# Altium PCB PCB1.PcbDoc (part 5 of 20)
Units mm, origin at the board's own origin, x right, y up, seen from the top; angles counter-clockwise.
Board outline 294.51 x 138.18 mm, 12 copper layers (Top Layer 1 _Signal, L2_GND, L3_Signals, L4_GND, L5_POWER, L6_Signals, L7_GND, L8_Signals, L9_GND, L10_POWER, L11_GND, Bottom Layer_Signals), stack 1.788 mm thick; 1254 components, 836 nets, 5699 pads, 2073 vias.
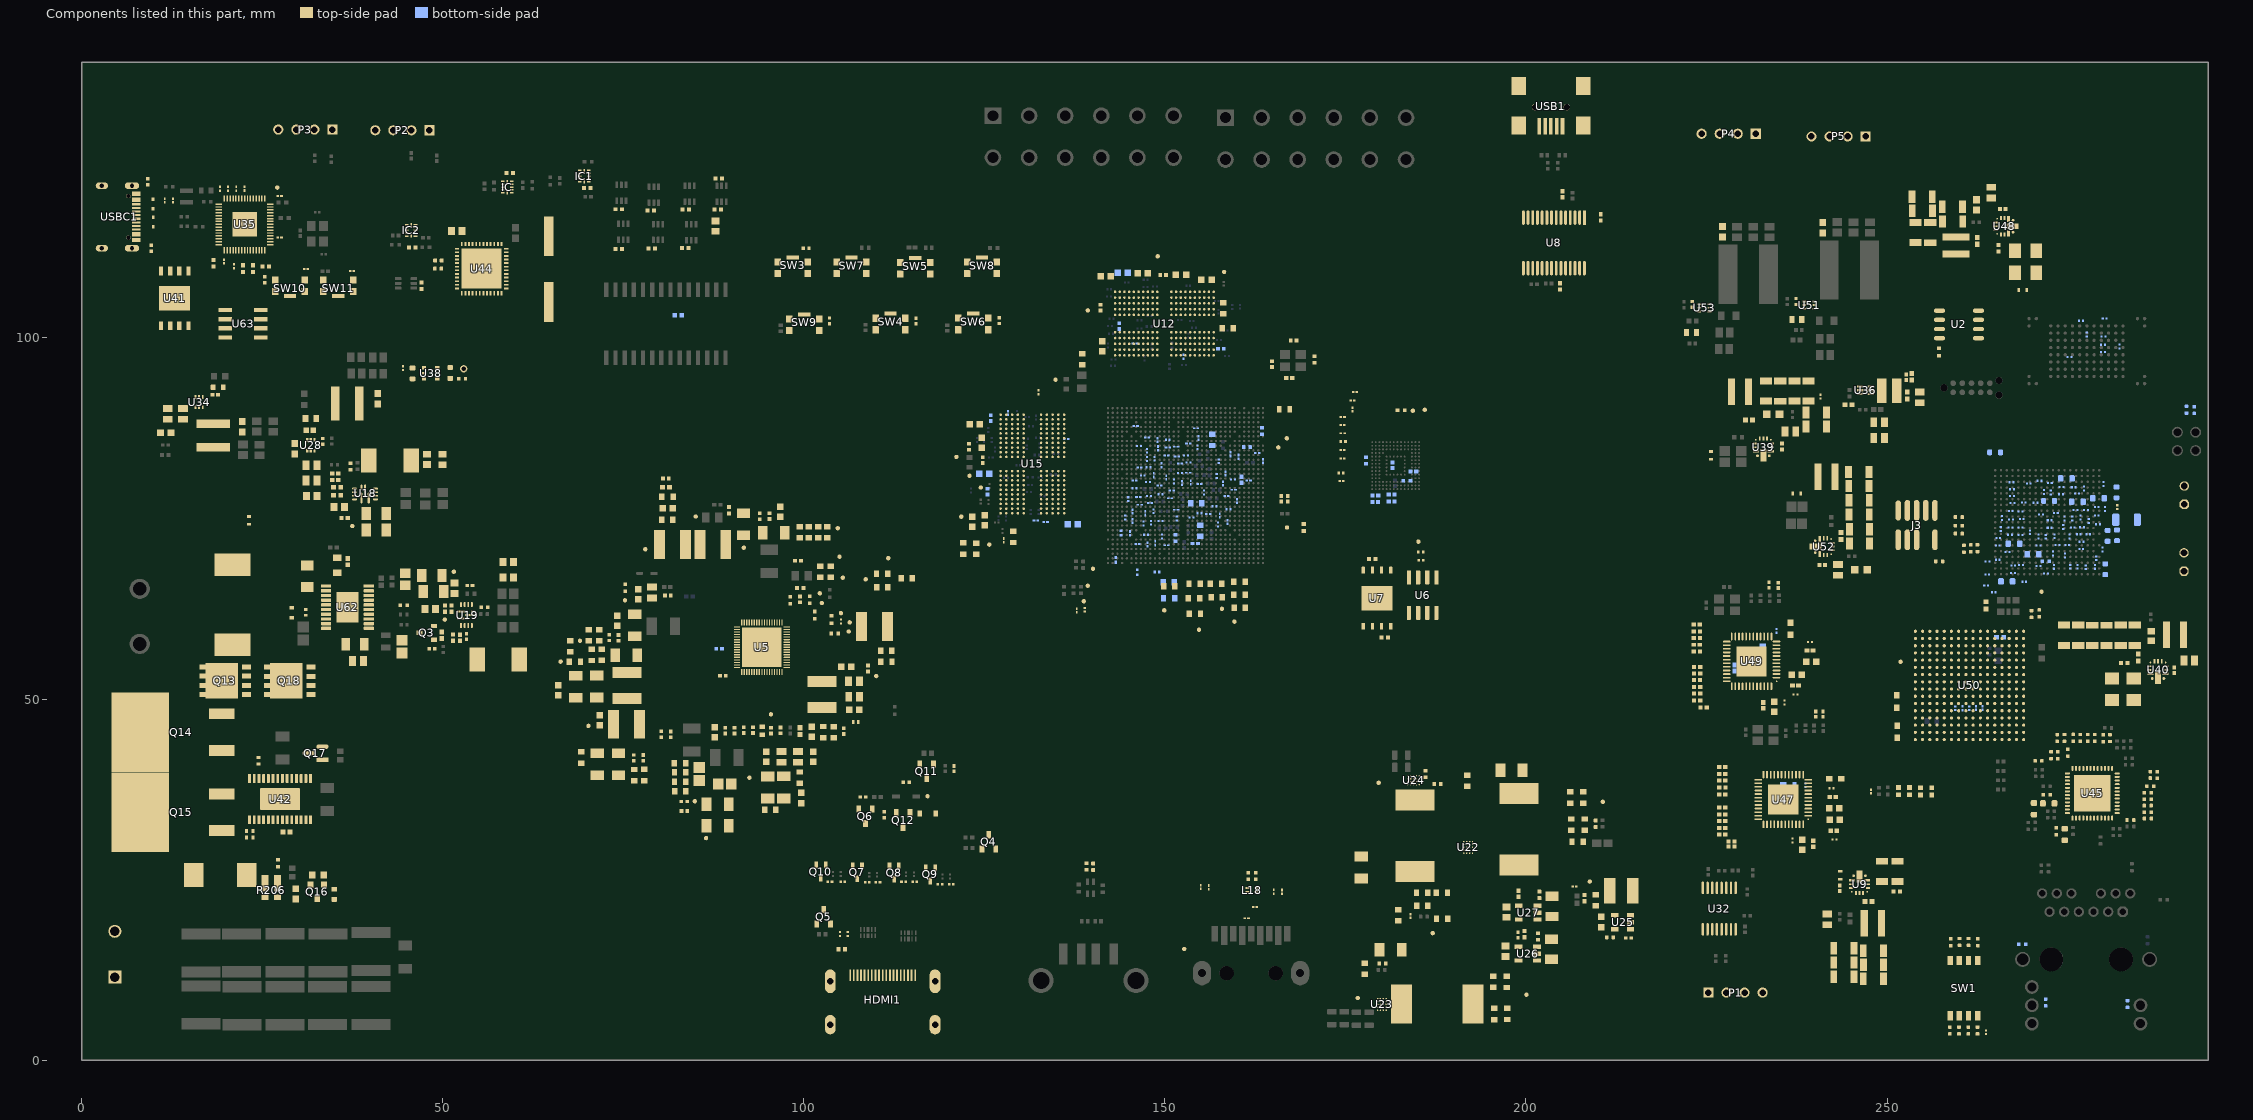
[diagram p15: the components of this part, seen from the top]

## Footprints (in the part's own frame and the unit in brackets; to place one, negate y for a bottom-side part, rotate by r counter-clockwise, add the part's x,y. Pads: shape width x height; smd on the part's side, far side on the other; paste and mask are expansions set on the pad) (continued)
FP-GRM155-0_1-MFG [mm]
  rect 0.4x0.5 smd paste+0 mask+0: 1(-0.4,0) 2(0.4,0)
  silkscreen extent -0.52,-0.62 0.52,0.63, body extent -0.7,-0.4 0.7,0.4, height 0.25
FP-GRM186-0_2-MFG [mm]
  rect 0.75x0.9 smd paste+0 mask+0: 1(-0.775,0) 2(0.775,0)
  silkscreen extent -0.02,-0.5 0.03,0.5, body extent -1.25,-0.6 1.25,0.6, height 0.25
FP-GRM188-0_1-e0_2_0_5-IPC_B [mm]
  rect 0.959x0.912 smd paste+0 mask+0: 1(-0.727,0) 2(0.727,0)
  silkscreen extent -1.21,-0.86 1.21,0.86, body extent -1.46,-0.71 1.46,0.71, height 0.25
FP-GRM188-0_2-MFG [mm]
  rect 0.75x0.9 smd paste+0 mask+0: 1(-0.775,0) 2(0.775,0)
  silkscreen extent -0.9,-0.9 0.9,0.9, body extent -0.8,-0.4 0.8,0.4, height 1
FP-KMR442G_ULC_LFS-MFG [mm]
  rect 0.9x1 smd paste+0 mask+0: 1(-2.05,0.8) 2(2.05,0.8) 3(-2.05,-0.8) 4(2.05,-0.8)
  rect 1.7x0.55 smd paste+0 mask+0: 5(0,1.425)
  silkscreen extent -3.22,-1.4 1.22,0.95, body extent -2.6,-1.5 2.6,1.8, height 0.25
FP-MCS0402-IPC_A [mm]
  rect 0.665x0.672 smd paste+0 mask+0: 1(-0.504,0) 2(0.504,0)
  silkscreen extent -0.84,-0.74 0.84,0.74, body extent -1.04,-0.54 1.04,0.54, height 0.25
FP-MCS0402-IPC_C [mm]
  rect 0.465x0.472 smd paste+0 mask+0: 1(-0.404,0) 2(0.404,0)
  silkscreen extent -0.64,-0.67 0.64,0.67, body extent -0.74,-0.38 0.74,0.38, height 0.25
FP-MCT0603-MFG [mm]
  rect 0.7x0.95 smd paste+0 mask+0: 1(-0.675,0) 2(0.675,0)
  silkscreen extent -0.8,-0.85 0.8,0.85, body extent -1.12,-0.58 1.12,0.58, height 0.25
FP-MCZ1210AH-MFG [mm]
  rect 0.3x0.5 smd paste+0 mask+0: 1(-0.275,-0.613) 2(0.275,-0.613) 3(0.275,0.612) 4(-0.275,0.612)
  silkscreen extent -0.83,-1.56 0.82,0.7, body extent -0.67,-0.96 0.67,0.96, height 0.25
FP-NRS5030-H_3_1-MFG [mm]
  rect 1.5x4 smd paste+0 mask+0: 1(-1.8,0) 2(1.8,0)
  silkscreen extent -2.55,-2.55 2.55,2.55, body extent -2.65,-2.65 2.65,2.65, height 0.25
FP-PS0612-MFG [mm]
  rect 1x0.8 smd paste+0 mask+0: 1(-0.875,1.35) 2(0.875,1.35)
  rect 1x2.32 smd paste+0 mask+0: 3(-0.875,-0.59) 4(0.875,-0.59)
  silkscreen extent -2.23,-2.25 0.88,2.22, body extent -1.48,-1.85 1.48,1.85, height 0.25
FP-RC0603-0_55-IPC_A [mm]
  rect 1.059x1.012 smd paste+0 mask+0: 1(-0.877,0) 2(0.877,0)
  silkscreen extent -1.41,-0.91 1.41,0.91, body extent -1.91,-1.01 1.91,1.01, height 0.25
FP-RC1005-IPC_A [mm]
  rect 0.715x0.672 smd paste+0 mask+0: 1(-0.479,0) 2(0.479,0)
  silkscreen extent -0.84,-0.74 0.84,0.74, body extent -1.04,-0.54 1.04,0.54, height 0.25
FP-RGZ0048B-IPC_A [mm]
  round 0.215 smd paste+0 mask+0: 1(-3.463,2.75)
  rrect100% 1.057x0.239 smd paste+0 mask+0: 2(-3.451,2.25) 3(-3.451,1.75) 4(-3.451,1.25) 5(-3.451,0.75) 6(-3.451,0.25) 7(-3.451,-0.25) 8(-3.451,-0.75) 9(-3.451,-1.25) 10(-3.451,-1.75) 11(-3.451,-2.25) 12(-3.451,-2.75) 25(3.451,-2.75) 26(3.451,-2.25) 27(3.451,-1.75) 28(3.451,-1.25) 29(3.451,-0.75) 30(3.451,-0.25) 31(3.451,0.25) 32(3.451,0.75) 33(3.451,1.25) 34(3.451,1.75) 35(3.451,2.25) 36(3.451,2.75)
  rrect100% 0.239x1.057 smd paste+0 mask+0: 13(-2.75,-3.451) 14(-2.25,-3.451) 15(-1.75,-3.451) 16(-1.25,-3.451) 17(-0.75,-3.451) 18(-0.25,-3.451) 19(0.25,-3.451) 20(0.75,-3.451) 21(1.25,-3.451) 22(1.75,-3.451) 23(2.25,-3.451) 24(2.75,-3.451) 37(2.75,3.451) 38(2.25,3.451) 39(1.75,3.451) 40(1.25,3.451) 41(0.75,3.451) 42(0.25,3.451) 43(-0.25,3.451) 44(-0.75,3.451) 45(-1.25,3.451) 46(-1.75,3.451) 47(-2.25,3.451) 48(-2.75,3.451)
  rect 4.2x4.2 smd paste-1000 mask+0: 49(0,0)
  Top Layer 1 _Signal region: -3.979,2.87 -3.042,2.87 -2.996,2.861 -2.957,2.835 -2.931,2.796 -2.922,2.75 -2.922,2.75 -2.938,2.69 -2.982,2.646 -3.042,2.63 -3.042,2.63 -3.979,2.63
  silkscreen extent -4.68,-3.5 3.5,3.5, body extent -4.48,-4.48 4.48,4.48, height 0.25
FP-RMCF0201-IPC_C [mm]
  rect 0.354x0.263 smd paste+0 mask+0: 1(-0.254,0) 2(0.254,0)
  silkscreen extent -0.43,-0.56 0.43,0.57, body extent -0.3,-0.15 0.3,0.15, height 0.26
FP-RMCF0603-IPC_B [mm]
  rect 1.006x0.958 smd paste+0 mask+0: 1(-0.701,0) 2(0.701,0)
  silkscreen extent -1.2,-0.88 1.2,0.88, body extent -1.45,-0.73 1.45,0.73, height 0.25
FP-RMCF0603-MFG [mm]
  rect 0.65x0.9 smd paste+0 mask+0: 1(-0.725,0) 2(0.725,0)
  silkscreen extent -0.85,-0.85 0.85,0.85, body extent -1.15,-0.58 1.15,0.58, height 0.25
FP-RN73R1E-IPC_B [mm]
  rect 0.588x0.572 smd paste+0 mask+0: 1(-0.464,0) 2(0.464,0)
  silkscreen extent -0.76,-0.69 0.76,0.69, body extent -0.91,-0.44 0.91,0.44, height 0.25
FP-RN73R1E-IPC_C [mm]
  rect 0.488x0.472 smd paste+0 mask+0: 1(-0.414,0) 2(0.414,0)
  silkscreen extent -0.66,-0.67 0.66,0.67, body extent -0.76,-0.38 0.76,0.38, height 0.25
FP-RNCP0805-IPC_A [mil]
  rect 59.27x59.38 smd paste+0 mask+0: 1(-34.5,0) 2(34.5,0)
  silkscreen extent -64,-45 64,45, body extent -84,-49 84,49, height 10
FP-RP73P-1E-MFG [mm]
  rect 0.5x0.6 smd paste+0 mask+0: 1(-0.5,0) 2(0.5,0)
  silkscreen extent -0.53,-0.77 0.53,0.75, body extent -0.85,-0.4 0.85,0.4, height 0.25
FP-RT0201-MFG [mm]
  rect 0.35x0.4 smd paste+0 mask+0: 1(-0.325,0) 2(0.325,0)
  silkscreen extent -0.32,-0.57 0.32,0.58, body extent -0.6,-0.3 0.6,0.3, height 0.25
FP-RT0402-MFG [mm]
  rect 0.5x0.6 smd paste+0 mask+0: 1(-0.5,0) 2(0.5,0)
  silkscreen extent -0.5,-0.71 0.5,0.7, body extent -0.85,-0.4 0.85,0.4, height 0.25
FP-RT0603-MFG [mm]
  rect 0.9x0.8 smd paste+0 mask+0: 1(-0.85,0) 2(0.85,0)
  silkscreen extent -0.85,-0.81 0.86,0.8, body extent -1.4,-0.55 1.4,0.55, height 0.25
FP-RT0805-MFG [mm]
  rect 0.9x1.2 smd paste+0 mask+0: 1(-1.05,0) 2(1.05,0)
  silkscreen extent -0.22,-0.68 0.23,0.67, body extent -1.6,-0.77 1.6,0.77, height 0.25
FP-SESD0402-MFG [mm]
  rect 0.35x0.6 smd paste+0 mask+0: 1(-0.325,0) 2(0.325,0)
  silkscreen extent -0.53,-0.71 0.52,0.7, body extent -0.63,-0.43 0.63,0.43, height 0.25
FP-SOD523-MFG [mm]
  rect 0.5x0.6 smd paste-1000 mask+0: 1(-0.7,0) 2(0.7,0)
  silkscreen extent -1.62,-0.43 0.08,0.43, body extent -1.07,-0.6 1.07,0.6, height 0.25
FP-SOT23-IPC_A [mm]
  rect 1.659x0.627 smd paste+0 mask+0: 1(-0.977,0.915)
  rrect100% 1.659x0.627 smd paste+0 mask+0: 2(-0.977,-0.915) 3(0.977,0)
  silkscreen extent 0.23,-1.45 0.65,1.45, body extent -2.31,-1.95 2.31,1.95, height 0.25
FP-SOT23-MFG [mm]
  rect 0.9x0.8 smd paste+0 mask+0: 1(-1,0.95) 2(-1,-0.95) 3(1,0)
  silkscreen extent -0.18,-1.5 0.7,1.5, body extent -1.55,-1.6 1.55,1.6, height 0.25
FP-SRP1265A-MFG [mm]
  rect 3.1x5 smd paste+0 mask+0: 1(-5.55,0) 2(5.55,0)
  silkscreen extent -7,-6.4 7,6.4, body extent -7.2,-6.5 7.2,6.5, height 0.25
FP-SS8050-G-MFG [mm]
  rect 0.8x0.6 smd paste+0 mask+0: 1(-1.01,0.95) 2(-1.01,-0.95) 3(1.01,0)
  silkscreen extent -0.7,-1.5 0.7,1.5, body extent -1.51,-1.6 1.51,1.6, height 0.25
FP-SSOP-28-MFG [mm]
  rect 2x0.4 smd paste+0 mask+0: 1(-3.5,4.225)
  rrect100% 2x0.4 smd paste+0 mask+0: 2(-3.5,3.575) 3(-3.5,2.925) 4(-3.5,2.275) 5(-3.5,1.625) 6(-3.5,0.975) 7(-3.5,0.325) 8(-3.5,-0.325) 9(-3.5,-0.975) 10(-3.5,-1.625) 11(-3.5,-2.275) 12(-3.5,-2.925) 13(-3.5,-3.575) 14(-3.5,-4.225) 15(3.5,-4.225) 16(3.5,-3.575) 17(3.5,-2.925) 18(3.5,-2.275) 19(3.5,-1.625) 20(3.5,-0.975) 21(3.5,-0.325) 22(3.5,0.325) 23(3.5,0.975) 24(3.5,1.625) 25(3.5,2.275) 26(3.5,2.925) 27(3.5,3.575) 28(3.5,4.225)
  silkscreen extent -5.3,-5.25 2.8,5.25, body extent -4.6,-5.55 4.6,5.55, height 0.25
FP-TFCR0603-IPC_B [mm]
  rect 0.958x0.912 smd paste+0 mask+0: 1(-0.702,0) 2(0.702,0)
  silkscreen extent -1.18,-0.86 1.18,0.86, body extent -1.43,-0.71 1.43,0.71, height 0.25
FP-VSC8504XKS-05-IPC_C [mm]
  round 0.436 smd paste+0 mask+0: A1(-7.5,7.5) A2(-6.5,7.5) A3(-5.5,7.5) A4(-4.5,7.5) A5(-3.5,7.5) A6(-2.5,7.5) A7(-1.5,7.5) A8(-0.5,7.5) A9(0.5,7.5) A10(1.5,7.5) A11(2.5,7.5) A12(3.5,7.5) A13(4.5,7.5) A14(5.5,7.5) A15(6.5,7.5) A16(7.5,7.5) B1(-7.5,6.5) B2(-6.5,6.5) B3(-5.5,6.5) B4(-4.5,6.5) B5(-3.5,6.5) B6(-2.5,6.5) B7(-1.5,6.5) B8(-0.5,6.5) B9(0.5,6.5) B10(1.5,6.5) B11(2.5,6.5) B12(3.5,6.5) B13(4.5,6.5) B14(5.5,6.5) B15(6.5,6.5) B16(7.5,6.5) C1(-7.5,5.5) C2(-6.5,5.5) C3(-5.5,5.5) C4(-4.5,5.5) C5(-3.5,5.5) C6(-2.5,5.5) C7(-1.5,5.5) C8(-0.5,5.5) C9(0.5,5.5) C10(1.5,5.5) C11(2.5,5.5) C12(3.5,5.5) C13(4.5,5.5) C14(5.5,5.5) C15(6.5,5.5) C16(7.5,5.5) D1(-7.5,4.5) D2(-6.5,4.5) D3(-5.5,4.5) D4(-4.5,4.5) D5(-3.5,4.5) D6(-2.5,4.5) D7(-1.5,4.5) D8(-0.5,4.5) D9(0.5,4.5) D10(1.5,4.5) D11(2.5,4.5) D12(3.5,4.5) D13(4.5,4.5) D14(5.5,4.5) D15(6.5,4.5) D16(7.5,4.5) E1(-7.5,3.5) E2(-6.5,3.5) E3(-5.5,3.5) E4(-4.5,3.5) E5(-3.5,3.5) E6(-2.5,3.5) E7(-1.5,3.5) E8(-0.5,3.5) E9(0.5,3.5) E10(1.5,3.5) E11(2.5,3.5) E12(3.5,3.5) E13(4.5,3.5) E14(5.5,3.5) E15(6.5,3.5) E16(7.5,3.5) F1(-7.5,2.5) F2(-6.5,2.5) F3(-5.5,2.5) F4(-4.5,2.5) F5(-3.5,2.5) F6(-2.5,2.5) F7(-1.5,2.5) F8(-0.5,2.5) F9(0.5,2.5) F10(1.5,2.5) F11(2.5,2.5) F12(3.5,2.5) F13(4.5,2.5) F14(5.5,2.5) F15(6.5,2.5) F16(7.5,2.5) G1(-7.5,1.5) G2(-6.5,1.5) G3(-5.5,1.5) G4(-4.5,1.5) G5(-3.5,1.5) G6(-2.5,1.5) G7(-1.5,1.5) G8(-0.5,1.5) G9(0.5,1.5) G10(1.5,1.5) G11(2.5,1.5) G12(3.5,1.5) G13(4.5,1.5) G14(5.5,1.5) G15(6.5,1.5) G16(7.5,1.5) H1(-7.5,0.5) H2(-6.5,0.5) H3(-5.5,0.5) H4(-4.5,0.5) H5(-3.5,0.5) H6(-2.5,0.5) H7(-1.5,0.5) H8(-0.5,0.5) H9(0.5,0.5) H10(1.5,0.5) H11(2.5,0.5) H12(3.5,0.5) H13(4.5,0.5) H14(5.5,0.5) H15(6.5,0.5) H16(7.5,0.5) J1(-7.5,-0.5) J2(-6.5,-0.5) J3(-5.5,-0.5) J4(-4.5,-0.5) J5(-3.5,-0.5) J6(-2.5,-0.5) J7(-1.5,-0.5) J8(-0.5,-0.5) J9(0.5,-0.5) J10(1.5,-0.5) J11(2.5,-0.5) J12(3.5,-0.5) J13(4.5,-0.5) J14(5.5,-0.5) J15(6.5,-0.5) J16(7.5,-0.5) K1(-7.5,-1.5) K2(-6.5,-1.5) K3(-5.5,-1.5) K4(-4.5,-1.5) K5(-3.5,-1.5) K6(-2.5,-1.5) K7(-1.5,-1.5) K8(-0.5,-1.5) K9(0.5,-1.5) K10(1.5,-1.5) K11(2.5,-1.5) K12(3.5,-1.5) K13(4.5,-1.5) K14(5.5,-1.5) K15(6.5,-1.5) K16(7.5,-1.5) L1(-7.5,-2.5) L2(-6.5,-2.5) L3(-5.5,-2.5) L4(-4.5,-2.5) L5(-3.5,-2.5) L6(-2.5,-2.5) L7(-1.5,-2.5) L8(-0.5,-2.5) L9(0.5,-2.5) L10(1.5,-2.5) L11(2.5,-2.5) L12(3.5,-2.5) L13(4.5,-2.5) L14(5.5,-2.5) L15(6.5,-2.5) L16(7.5,-2.5) M1(-7.5,-3.5) M2(-6.5,-3.5) M3(-5.5,-3.5) M4(-4.5,-3.5) M5(-3.5,-3.5) M6(-2.5,-3.5) M7(-1.5,-3.5) M8(-0.5,-3.5) M9(0.5,-3.5) M10(1.5,-3.5) M11(2.5,-3.5) M12(3.5,-3.5) M13(4.5,-3.5) M14(5.5,-3.5) M15(6.5,-3.5) M16(7.5,-3.5) N1(-7.5,-4.5) N2(-6.5,-4.5) N3(-5.5,-4.5) N4(-4.5,-4.5) N5(-3.5,-4.5) N6(-2.5,-4.5) N7(-1.5,-4.5) N8(-0.5,-4.5) N9(0.5,-4.5) N10(1.5,-4.5) N11(2.5,-4.5) N12(3.5,-4.5) N13(4.5,-4.5) N14(5.5,-4.5) N15(6.5,-4.5) N16(7.5,-4.5) P1(-7.5,-5.5) P2(-6.5,-5.5) P3(-5.5,-5.5) P4(-4.5,-5.5) P5(-3.5,-5.5) P6(-2.5,-5.5) P7(-1.5,-5.5) P8(-0.5,-5.5) P9(0.5,-5.5) P10(1.5,-5.5) P11(2.5,-5.5) P12(3.5,-5.5) P13(4.5,-5.5) P14(5.5,-5.5) P15(6.5,-5.5) P16(7.5,-5.5) R1(-7.5,-6.5) R2(-6.5,-6.5) R3(-5.5,-6.5) R4(-4.5,-6.5) R5(-3.5,-6.5) R6(-2.5,-6.5) R7(-1.5,-6.5) R8(-0.5,-6.5) R9(0.5,-6.5) R10(1.5,-6.5) R11(2.5,-6.5) R12(3.5,-6.5) R13(4.5,-6.5) R14(5.5,-6.5) R15(6.5,-6.5) R16(7.5,-6.5) T1(-7.5,-7.5) T2(-6.5,-7.5) T3(-5.5,-7.5) T4(-4.5,-7.5) T5(-3.5,-7.5) T6(-2.5,-7.5) T7(-1.5,-7.5) T8(-0.5,-7.5) T9(0.5,-7.5) T10(1.5,-7.5) T11(2.5,-7.5) T12(3.5,-7.5) T13(4.5,-7.5) T14(5.5,-7.5) T15(6.5,-7.5) T16(7.5,-7.5)
  silkscreen extent -8.92,-8.5 8.5,8.5, body extent -8.6,-8.6 8.6,8.6, height 0.25
FP-XAL5030-222MEB-MFG [mm]
  rect 1.18x4.7 smd paste+0 mask+0: 1(-1.655,0) 2(1.655,0)
  silkscreen extent -2.74,-2.84 2.74,2.84, body extent -2.84,-2.94 2.84,2.94, height 0.25
HC-49S_L11.4-W4.5-LS12.5 [mm]
  rect 5.5x1.3 smd paste+0 mask+0.051: 1(4.553,0) 2(-4.553,0)
  silkscreen extent -5.72,-2.41 5.71,2.41
HDMI-SMD_HDMI-019S [mm]
  rect 0.25x1.6 smd paste-100 mask+0.05: 1(4.501,5.328) 2(4.001,5.328) 3(3.501,5.328) 4(3,5.328) 5(2.5,5.328) 6(2,5.328) 7(1.5,5.328) 8(1,5.328) 9(0.5,5.328) 10(0,5.328) 11(-0.5,5.328) 12(-1,5.328) 13(-1.5,5.328) 14(-2,5.328) 15(-2.5,5.328) 16(-3.001,5.328) 17(-3.501,5.328) 18(-4.001,5.328) 19(-4.501,5.328)
  oval 1.5x2.7 hole 0.9 slot 2.1 at 90 deg paste-2539.97 mask+0.05: 20(7.251,-1.505) 21(-7.251,-1.505)
  oval 1.5x3.3 hole 0.9 slot 2.7 at 90 deg paste-2539.97 mask+0.05: 22(7.251,4.495) 23(-7.251,4.495)
  silkscreen extent -7.5,-6.1 7.5,5.49
HDR_M_1.27_2x5_SMD_V_SAM_FTSH-105-01-F-DV-007-K [mil]
  oval 30x114 smd: 1(-100,-80) 3(-50,-80) 4(-50,80) 5(0,-80) 6(0,80) 8(50,80) 9(100,-80) 10(100,80)
  oval 29.13x109.84 smd: 2(-100,80)
  silkscreen extent -162,-150 134,75, body extent -125,-175 125,115, height 275
HDR_M_2.54_1x2 [mil] "Header Male Vertical 2 Way 2.54mm Pitch"
  oct 51x51 hole 36: 1(0,0)
  round 51 hole 36: 2(100,0)
  silkscreen extent -74,-74 160,57, body extent -50,-49 150,49, height 330
HRO_TYPE-C-31-M-12 [mm]
  rect 0.6x1.14 smd mask+0.05: A1_B12(-3.2,4.75) A4_B9(-2.4,4.75) B1_A12(3.2,4.75) B4_A9(2.4,4.75)
  rect 0.3x1.14 smd mask+0.05: A5(-1.25,4.75) A6(-0.25,4.75) A7(0.25,4.75) A8(1.25,4.75) B5(1.75,4.75) B6(0.75,4.75) B7(-0.75,4.75) B8(-1.75,4.75)
  oval 0.9x2 hole 0.6 slot 1.7 at 90 deg: S1(-4.325,4.17) S2(4.325,4.17)
  oval 0.9x1.7 hole 0.6 slot 1.4 at 90 deg: S3(-4.325,0) S4(4.325,0)
  round 0.6 hole 0.6 unplated: ""(-2.89,3.68) ""(2.89,3.68)
  silkscreen extent -4.47,-2.6 4.47,6.1, body extent -4.47,-2.6 4.47,5.31, height 3.31
IND-SMD_L4.0-W4.0 [mm]
  rect 1.6x3.5 smd paste+0 mask+0.051: 1(-1.6,0) 2(1.6,0)
  silkscreen extent -2.08,-2.1 2.08,2.1
IND-SMD_L7.1-W6.6 [mm]
  rect 2.15x3.32 smd paste+0 mask+0.051: 1(-2.913,0) 2(2.913,0)
  silkscreen extent -3.3,-3.3 3.3,3.3
IND_C_0603 [mm] "Chip Inductor, 2-Leads, Body 1.6x0.8mm, IPC Medium Density"
  rrect50% 0.8x0.9 smd: 1(-0.8,0) 2(0.8,0)
  silkscreen extent -0.1,-0.35 0.1,0.35, body extent -0.8,-0.4 0.8,0.4, height 0.95
IND_C_1206 [mm] "Chip Inductor, 2-Leads, L3.2W1.6H1.1mm, IPC Medium Density"
  rrect50% 1x1.75 smd: 1(-1.5,0) 2(1.5,0)
  silkscreen extent -0.6,-0.77 0.6,0.78, body extent -1.6,-0.8 1.6,0.8, height 1.1
JST-S4B-XH-A(LF)(SN)_V [mm] "Header, 4-Leads, Body 12.4x11.5mm, Pitch 2.5mm"
  rect 1.4x1.4 hole 0.9: 1(-3.75,0)
  round 1.4 hole 0.9: 2(-1.25,0) 3(1.25,0) 4(3.75,0)
  silkscreen extent -6.2,-9.2 6.2,3.08, body extent -6.2,-9.2 6.2,2.3, height 6.15
JUMPER [mm]
  rect 0.65x0.55 smd paste-2.54 mask-2.54: 1(0,-0.45) 2(0,0.55)
  Top Layer 1 _Signal region: -0.325,-0.041 0,0.284 0.325,-0.041 0.325,0.318 -0.325,0.317
  Top Layer 1 _Signal region: -0.325,-0.175 0.003,0.152 0.325,-0.175
MINI-USB-SMD_XY-5PTP-MINIUSB [mm]
  rect 0.5x2.3 smd paste+0 mask+0.05: 1(-1.6,3.746) 2(-0.8,3.746) 3(0,3.746) 4(0.8,3.746) 5(1.6,3.746)
  rect 2x2.5 smd paste+0 mask+0.05: 6(4.45,3.646) 7(-4.45,3.646) 8(-4.45,-1.854) 9(4.45,-1.854)
  round 0.9 hole 0.9 unplated paste-2539.97: ""(-2.2,1.096) ""(2.2,1.096)
  silkscreen extent -3.75,-4.77 3.75,4.27
ONSC-SOD-323-2-477-02_V [mm] "SOD, 2-Leads, Body 1.7x1.25mm"
  rect 0.63x0.83 smd: 1(-1.115,0) 2(1.115,0)
  silkscreen extent -1.24,-0.67 0.4,1.09, body extent -0.85,-0.63 0.85,0.63, height 1.06
PHOE-1714955_V [mm] "Terminal Block, 2-Leads, Body 12.7x12.5mm, Pitch 6.35mm"
  rect 1.8x1.8 hole 1.3: 1(-3.175,0)
  round 1.8 hole 1.3: 2(3.175,0)
  silkscreen extent -6.35,-8.68 6.35,4.6, body extent -6.92,-7.9 6.35,4.6, height 21.51
PWP0020A_N [mm] "SOP, 20-Leads, Body 6.6x4.5mm, Pitch 0.65mm, Thermal Pad 4.2x3mm, IPC Medium Density"
  rrect22% 1.4x0.45 smd: 1(-2.95,2.925) 2(-2.95,2.275) 3(-2.95,1.625) 4(-2.95,0.975) 5(-2.95,0.325) 6(-2.95,-0.325) 7(-2.95,-0.975) 8(-2.95,-1.625) 9(-2.95,-2.275) 10(-2.95,-2.925) 11(2.95,-2.925) 12(2.95,-2.275) 13(2.95,-1.625) 14(2.95,-0.975) 15(2.95,-0.325) 16(2.95,0.325) 17(2.95,0.975) 18(2.95,1.625) 19(2.95,2.275) 20(2.95,2.925)
  rrect3% 3x4.2 smd: 21(0,0)
  silkscreen extent -3.08,-3.3 1.85,3.82, body extent -3.21,-3.25 3.21,3.25, height 1
PWP0028A_L [mm] "SOP, 28-leads, Body 4.5x9.8mm, Pitch 0.65mm, Thermal Pad 3x5.5mm, IPC High Density"
  rrect25% 1.2x0.4 smd: 1(-2.85,4.225) 2(-2.85,3.575) 3(-2.85,2.925) 4(-2.85,2.275) 5(-2.85,1.625) 6(-2.85,0.975) 7(-2.85,0.325) 8(-2.85,-0.325) 9(-2.85,-0.975) 10(-2.85,-1.625) 11(-2.85,-2.275) 12(-2.85,-2.925) 13(-2.85,-3.575) 14(-2.85,-4.225) 15(2.85,-4.225) 16(2.85,-3.575) 17(2.85,-2.925) 18(2.85,-2.275) 19(2.85,-1.625) 20(2.85,-0.975) 21(2.85,-0.325) 22(2.85,0.325) 23(2.85,0.975) 24(2.85,1.625) 25(2.85,2.275) 26(2.85,2.925) 27(2.85,3.575) 28(2.85,4.225)
  rrect3% 3x5.5 smd: 29(0,0)
  silkscreen extent -2.97,-4.9 1.85,5.1, body extent -3.21,-4.85 3.21,4.85, height 0.98
QFN35P700X700X90-69N [mm]
  rrect25% 0.84x0.17 smd paste+0 mask+0.102: 1(-3.445,2.8) 2(-3.445,2.45) 3(-3.445,2.1) 4(-3.445,1.75) 5(-3.445,1.4) 6(-3.445,1.05) 7(-3.445,0.7) 8(-3.445,0.35) 9(-3.445,0) 10(-3.445,-0.35) 11(-3.445,-0.7) 12(-3.445,-1.05) 13(-3.445,-1.4) 14(-3.445,-1.75) 15(-3.445,-2.1) 16(-3.445,-2.45) 17(-3.445,-2.8) 35(3.445,-2.8) 36(3.445,-2.45) 37(3.445,-2.1) 38(3.445,-1.75) 39(3.445,-1.4) 40(3.445,-1.05) 41(3.445,-0.7) 42(3.445,-0.35) 43(3.445,0) 44(3.445,0.35) 45(3.445,0.7) 46(3.445,1.05) 47(3.445,1.4) 48(3.445,1.75) 49(3.445,2.1) 50(3.445,2.45) 51(3.445,2.8)
  rrect25% 0.17x0.84 smd paste+0 mask+0.102: 18(-2.8,-3.445) 19(-2.45,-3.445) 20(-2.1,-3.445) 21(-1.75,-3.445) 22(-1.4,-3.445) 23(-1.05,-3.445) 24(-0.7,-3.445) 25(-0.35,-3.445) 26(0,-3.445) 27(0.35,-3.445) 28(0.7,-3.445) 29(1.05,-3.445) 30(1.4,-3.445) 31(1.75,-3.445) 32(2.1,-3.445) 33(2.45,-3.445) 34(2.8,-3.445) 52(2.8,3.445) 53(2.45,3.445) 54(2.1,3.445) 55(1.75,3.445) 56(1.4,3.445) 57(1.05,3.445) 58(0.7,3.445) 59(0.35,3.445) 60(0,3.445) 61(-0.35,3.445) 62(-0.7,3.445) 63(-1.05,3.445) 64(-1.4,3.445) 65(-1.75,3.445) 66(-2.1,3.445) 67(-2.45,3.445) 68(-2.8,3.445)
  rect 5.49x5.49 smd paste-4 mask+0.102: 69(0,0)
  silkscreen extent -4.58,-3.5 3.5,3.5
QFN40P170X200X50-12N [mm]
  rect 0.5x0.2 smd: 1(-0.6,0.8) 2(-0.6,0.4) 3(-0.6,0) 4(-0.6,-0.4) 5(-0.6,-0.8) 7(0.6,-0.8) 8(0.6,-0.4) 9(0.6,0) 10(0.6,0.4) 11(0.6,0.8)
  rect 0.2x0.5 smd: 6(0,-0.75) 12(0,0.75)
QFN-12_L3.0-W2.0-P0.5-TL_NB680 [mm]
  oval 1.5x0.3 smd paste+0 mask+0.051: 1(-0.425,0.5) 2(-0.425,-0.5) 7(0.675,0)
  oval 0.25x0.7 smd paste+0 mask+0.051: 3(-0.625,-1.45) 4(-0.125,-1.45) 5(0.375,-1.45) 6(0.875,-1.45) 9(0.875,1.45) 10(0.375,1.45) 11(-0.125,1.45) 12(-0.625,1.45)
  oval 0.7x0.25 smd paste+0 mask+0.051: 8(1.075,0.5)
  silkscreen extent -1.42,-1.65 1.27,1.65
QFN-48_7x7_EP5.1x5.1 [mm]
  oval 0.7x0.28 smd mask+0.05: 1(-3.45,2.75) 2(-3.45,2.25) 3(-3.45,1.75) 4(-3.45,1.25) 5(-3.45,0.75) 6(-3.45,0.25) 7(-3.45,-0.25) 8(-3.45,-0.75) 9(-3.45,-1.25) 10(-3.45,-1.75) 11(-3.45,-2.25) 12(-3.45,-2.75) 25(3.45,-2.75) 26(3.45,-2.25) 27(3.45,-1.75) 28(3.45,-1.25) 29(3.45,-0.75) 30(3.45,-0.25) 31(3.45,0.25) 32(3.45,0.75) 33(3.45,1.25) 34(3.45,1.75) 35(3.45,2.25) 36(3.45,2.75)
  oval 0.28x0.7 smd mask+0.05: 13(-2.75,-3.45) 14(-2.25,-3.45) 15(-1.75,-3.45) 16(-1.25,-3.45) 17(-0.75,-3.45) 18(-0.25,-3.45) 19(0.25,-3.45) 20(0.75,-3.45) 21(1.25,-3.45) 22(1.75,-3.45) 23(2.25,-3.45) 24(2.75,-3.45) 37(2.75,3.45) 38(2.25,3.45) 39(1.75,3.45) 40(1.25,3.45) 41(0.75,3.45) 42(0.25,3.45) 43(-0.25,3.45) 44(-0.75,3.45) 45(-1.25,3.45) 46(-1.75,3.45) 47(-2.25,3.45) 48(-2.75,3.45)
  rect 5.1x5.1 smd paste-5.1 mask+0.05: 49(0,0)
  silkscreen extent -3.85,-3.65 3.65,3.85, body extent -3.5,-3.5 3.5,3.5, height 0.87
QFN-60_L7.0-W7.0-P0.40-TL-EP3.4 [mm]
  rect 0.875x0.2 smd paste-100 mask+0.051: 1(-3.422,2.8) 2(-3.422,2.4) 3(-3.422,2) 4(-3.422,1.6) 5(-3.422,1.2) 6(-3.422,0.8) 7(-3.422,0.4) 8(-3.422,0) 9(-3.422,-0.4) 10(-3.422,-0.8) 11(-3.422,-1.2) 12(-3.422,-1.6) 13(-3.422,-2) 14(-3.422,-2.4) 15(-3.422,-2.8) 31(3.728,-2.8) 32(3.728,-2.4) 33(3.728,-2) 34(3.728,-1.6) 35(3.728,-1.2) 36(3.728,-0.8) 37(3.728,-0.4) 38(3.728,0) 39(3.728,0.4) 40(3.728,0.8) 41(3.728,1.2) 42(3.728,1.6) 43(3.728,2) 44(3.728,2.4) 45(3.728,2.8)
  rect 0.2x0.875 smd paste-100 mask+0.051: 16(-2.647,-3.575) 17(-2.247,-3.575) 18(-1.847,-3.575) 19(-1.447,-3.575) 20(-1.047,-3.575) 21(-0.647,-3.575) 22(-0.247,-3.575) 23(0.153,-3.575) 24(0.553,-3.575) 25(0.953,-3.575) 26(1.353,-3.575) 27(1.753,-3.575) 28(2.153,-3.575) 29(2.553,-3.575) 30(2.953,-3.575) 46(2.953,3.575) 47(2.553,3.575) 48(2.153,3.575) 49(1.753,3.575) 50(1.353,3.575) 51(0.953,3.575) 52(0.553,3.575) 53(0.153,3.575) 54(-0.247,3.575) 55(-0.647,3.575) 56(-1.047,3.575) 57(-1.447,3.575) 58(-1.847,3.575) 59(-2.247,3.575) 60(-2.647,3.575)
  rect 3.4x3.4 smd paste-100 mask+0.051: 61(0.153,0)
  silkscreen extent -4.17,-3.6 3.75,3.68
RES_C_0402 [mil] "Chip Resistor, 2-Leads, Body 1.0x0.5mm, IPC Medium Density"
  rrect33% 18.7x20 smd mask+2: 1(-18.68,0) 2(18.66,-0.07)
  silkscreen extent -4,-10 4,10, body extent -20,-10 20,10, height 13
RES_C_0603 [mm] "Chip Resistor, 2-Leads, Body 1.6x0.8mm, IPC Medium Density"
  rrect50% 0.7x0.8 smd: 1(-0.75,0) 2(0.75,0)
  silkscreen extent -0.1,-0.38 0.1,0.38, body extent -0.8,-0.4 0.8,0.4, height 0.3
RESC0201(0603)_L [mm] "Chip Resistor, Body 0.6x0.3mm, IPC High Density"
  rect 0.35x0.35 smd: 1(-0.3,0) 2(0.3,0)
  body extent -0.31,-0.16 0.31,0.16, height 0.3
RESC0402(1005)_L#1 [mm] "Chip Resistor, Body 1.0x0.5mm, IPC High Density"
  rrect25% 0.5x0.55 smd: 1(-0.45,0) 2(0.45,0)
  silkscreen extent 0,-0.2 0,0.2, body extent -0.5,-0.25 0.5,0.25, height 0.3
RESC0402(1005)_L#2 [mm] "Chip Resistor, Body 1.0x0.5mm, IPC High Density"
  rect 0.45x0.55 smd: 1(-0.45,0) 2(0.45,0)
  body extent -0.52,-0.27 0.53,0.28, height 0.4
RESC0402(1005)_M [mm] "Chip Resistor, Body 1.0x0.5mm, IPC Low Density"
  rect 0.65x0.75 smd: 1(-0.55,0) 2(0.55,0)
  body extent -0.52,-0.28 0.53,0.28, height 0.4
RESC0603(1608)_L [mm] "Chip Resistor, Body 1.6x0.8mm, IPC High Density"
  rrect25% 0.66x0.76 smd: 1(-0.7,0) 2(0.7,0)
  silkscreen extent 0,-0.3 0,0.3, body extent -0.8,-0.4 0.8,0.4, height 0.45
RESC0603(1608)_N [mm] "Chip Resistor, Body 1.6x0.8mm, IPC Medium Density"
  rect 0.9x1 smd: 1(-0.8,0) 2(0.8,0)
  silkscreen extent -0.05,-0.4 0.05,0.4, body extent -0.85,-0.47 0.85,0.47, height 0.6
RESC0603X26X15ML03T05 [mm] "Chip Resistor, 2-Leads, Body 0.60x0.30mm, IPC Low Density"
  rect 0.55x0.45 smd: 1(-0.375,0) 2(0.375,0)
  body extent -0.32,-0.16 0.32,0.17, height 0.26
RESC0603X28X15LL05T05 [mm] "Chip Resistor, 2-Leads, Body 0.60x0.30mm, IPC High Density"
  rect 0.35x0.25 smd: 1(-0.275,0) 2(0.275,0)
  body extent -0.33,-0.17 0.32,0.18, height 0.28
RESC0603X28X15NL05T05 [mm] "Chip Resistor, 2-Leads, Body 0.60x0.30mm, IPC Medium Density"
  rect 0.45x0.35 smd: 1(-0.325,0) 2(0.325,0)
  body extent -0.33,-0.17 0.33,0.18, height 0.28
RESC1005X35X20ML05T10 [mm] "Chip Resistor, 2-Leads, Body 1.00x0.50mm, IPC Low Density"
  rect 0.65x0.65 smd: 1(-0.5,0) 2(0.5,0)
  body extent -0.53,-0.27 0.53,0.28, height 0.35
RESC1005X40X20NL05T10 [mm] "Chip Resistor, 2-Leads, Body 1.00x0.50mm, IPC Medium Density"
  rect 0.55x0.55 smd: 1(-0.45,0) 2(0.45,0)
  body extent -0.53,-0.27 0.53,0.28, height 0.4
RESC1005X40X25LL05T05 [mm] "Chip Resistor, 2-Leads, Body 1.00x0.50mm, IPC High Density"
  rect 0.45x0.45 smd: 1(-0.4,0) 2(0.4,0)
  body extent -0.53,-0.27 0.53,0.28, height 0.4
RESC1005X40X25LL05T10 [mm] "Chip Resistor, 2-Leads, Body 1.00x0.50mm, IPC High Density"
  rect 0.5x0.45 smd: 1(-0.375,0) 2(0.375,0)
  body extent -0.53,-0.27 0.53,0.28, height 0.4
RESC1005X40X25ML05T05 [mm] "Chip Resistor, 2-Leads, Body 1.00x0.50mm, IPC Low Density"
  rect 0.65x0.65 smd: 1(-0.5,0) 2(0.5,0)
  body extent -0.53,-0.27 0.53,0.28, height 0.4
RESC1005X40X25ML05T10 [mm] "Chip Resistor, 2-Leads, Body 1.00x0.50mm, IPC Low Density"
  rect 0.7x0.65 smd: 1(-0.475,0) 2(0.475,0)
  body extent -0.53,-0.27 0.53,0.28, height 0.4
RESC1005X40X25ML10T10 [mm] "Chip Resistor, 2-Leads, Body 1.00x0.50mm, IPC Low Density"
  rect 0.75x0.7 smd: 1(-0.475,0) 2(0.475,0)
  body extent -0.55,-0.3 0.55,0.3, height 0.4
RESC1005X40X25NL05T05 [mm] "Chip Resistor, 2-Leads, Body 1.00x0.50mm, IPC Medium Density"
  rect 0.55x0.55 smd: 1(-0.45,0) 2(0.45,0)
  body extent -0.53,-0.27 0.53,0.28, height 0.4
RESC1005X40X25NL05T10 [mm] "Chip Resistor, 2-Leads, Body 1.00x0.50mm, IPC Medium Density"
  rect 0.6x0.55 smd: 1(-0.425,0) 2(0.425,0)
  body extent -0.53,-0.27 0.53,0.28, height 0.4
RESC1608X55X25ML10T15 [mm] "Chip Resistor, 2-Leads, Body 1.70x0.90mm, IPC Low Density"
  rect 0.8x1 smd: 1(-0.75,0) 2(0.75,0)
  body extent -0.85,-0.45 0.85,0.45, height 0.55
RESC1609X50X30ML10T20 [mm] "Chip Resistor, 2-Leads, Body 1.55x0.85mm, IPC Low Density"
  rect 0.9x1.05 smd: 1(-0.675,0) 2(0.675,0)
  body extent -0.82,-0.48 0.82,0.48, height 0.5
RESC3116X70X50ML13T20 [mm] "Chip Resistor, 2-Leads, Body 3.25x1.65mm, IPC Low Density"
  rect 1.4x1.75 smd: 1(-1.5,0) 2(1.5,0)
  silkscreen extent -0.4,-0.78 0.4,0.77, body extent -1.63,-0.82 1.63,0.82, height 0.7
RESC3216X60X45ML15T20 [mm] "Chip Resistor, 2-Leads, Body 3.3x1.75mm, IPC Low Density"
  rect 1.35x1.85 smd: 1(-1.525,0) 2(1.525,0)
  silkscreen extent -0.45,-0.82 0.45,0.83, body extent -1.65,-0.87 1.65,0.87, height 0.6
RPY0014A-MFG [mm]
  round 0.226 smd paste-0.1 mask-0.102: 1(-1.233,1.055) 5(-1.233,-1.055)
  rect 0.575x0.25 smd paste+0 mask-0.279: 2(-1.413,0.5) 3(-1.413,0) 4(-1.413,-0.5)
  rect 0.25x0.575 smd paste+0 mask-0.279: 6(-0.7,-1.163) 7(-0.2,-1.163) 13(-0.2,1.163) 14(-0.7,1.163)
  rect 0.35x0.85 smd paste+0 mask-0.406: 8(0.35,-1.025) 12(0.35,1.025)
  round 0.382 smd paste-0.179 mask-0.178: 9(0.987,-0.812) 11(0.987,0.812)
  rect 1.675x0.8 smd paste-0.825 mask-0.826: 10(0.913,0)
  Top Layer 1 _Signal region: 0.775,-1.4 0.775,-0.65 0.825,-0.6 1.65,-0.6 1.7,-0.65 1.7,-0.95 1.65,-1 1.175,-1 1.175,-1.4 1.125,-1.45 0.825,-1.45
  Top Layer 1 _Signal region: 0.775,1.4 0.775,0.65 0.825,0.6 1.65,0.6 1.7,0.65 1.7,0.95 1.65,1 1.175,1 1.175,1.4 1.125,1.45 0.825,1.45
  Top Layer 1 _Signal region: -1.7,0.925 -1.7,1.05 -1.65,1.1 -1.35,1.1 -1.35,1.4 -1.3,1.45 -1.125,1.45 -1.075,1.4 -1.075,0.925 -1.125,0.875 -1.65,0.875
  Top Layer 1 _Signal region: -1.7,-0.925 -1.7,-1.05 -1.65,-1.1 -1.35,-1.1 -1.35,-1.4 -1.3,-1.45 -1.125,-1.45 -1.075,-1.4 -1.075,-0.925 -1.125,-0.875 -1.65,-0.875
  silkscreen extent -2.4,-1.63 1.92,1.63
SC-70-5 [mil] "SC-70-5"
  rect 20x22 smd: 1(-29.53,-36.42) 3(29.53,-36.42) 4(29.53,36.42) 5(-29.53,36.42)
  rect 16x22 smd: 2(0,-36.42)
  silkscreen extent -60,-25 50,20, body extent -39,-41 39,41, height 37
SMC_L6.9-W5.9-LS7.9-RD [mm]
  rect 2.7x3.3 smd paste+0 mask+0.051: 1(-3.686,0) 2(3.686,0)
  silkscreen extent -4.36,-3.1 3.98,3.1
SOIC127P600X175-8N [mm]
  rrect25% 1.9x0.6 smd: 1(-2.455,1.905) 2(-2.455,0.635) 3(-2.455,-0.635) 4(-2.455,-1.905) 5(2.455,-1.905) 6(2.455,-0.635) 7(2.455,0.635) 8(2.455,1.905)
  silkscreen extent -4.07,-2.53 1.95,2.53, body extent -3,-2.45 3,2.45, height 1.75
SOIC-8 [mm] "SOIC, 8-Leads, Overall 4.9x6mm, Pitch 1.27mm, IPC Medium Density"
  oval 1.55x0.6 smd: 1(-2.7,1.905) 2(-2.7,0.635) 3(-2.7,-0.635) 4(-2.7,-1.905) 5(2.7,-1.905) 6(2.7,-0.635) 7(2.7,0.635) 8(2.7,1.905)
  silkscreen extent -2.25,-2.5 1.6,2.95, body extent -3.01,-2.5 3.01,2.5, height 1.75
SON127P600X800X80-9N [mm]
  rrect25% 0.94x0.44 smd: 1(-3.895,1.905) 2(-3.895,0.635) 3(-3.895,-0.635) 4(-3.895,-1.905) 5(3.895,-1.905) 6(3.895,-0.635) 7(3.895,0.635) 8(3.895,1.905)
  rect 3.4x4.3 smd paste-3: 9(0,0)
  silkscreen extent -5.1,-3 4,3, body extent -4,-3 4,3, height 0.8
SOT-5X3-6_W1.6-L1.2-P0.50-LS1.6-BL [mm]
  rect 0.25x0.5 smd paste+0 mask+0.051: 1(-0.368,-0.632) 2(0.132,-0.632) 3(0.632,-0.632) 4(0.634,0.768) 5(0.132,0.768) 6(-0.368,0.768)
  silkscreen extent -1.11,-0.92 0.98,0.57
SOT-23-3_L2.9-W1.3-P1.90-LS2.4-BR [mm]
  rect 1x0.65 smd paste+0 mask+0.051: 1(431.629,-422.514) 2(431.629,-420.614) 3(429.629,-421.564)
  silkscreen extent 429.9,-423.09 431.36,-420.04
SOT-23-5_L2.9-W1.6-P0.95-LS2.8-BL [mm]
  rect 0.6x1 smd paste+0 mask+0.05: 1(-0.886,-0.936) 2(0.064,-0.936) 3(1.013,-0.936) 4(1.014,1.264) 5(-0.886,1.264)
  silkscreen extent -1.46,-0.53 1.46,1.05
SOT-23-5_L2.9-W1.6-P0.95-LS2.8-TL [mm]
  rect 1.1x0.6 smd paste+0 mask+0.05: 1(-1.146,0.951) 2(-1.145,0.001) 3(-1.146,-0.949) 4(1.455,-0.949) 5(1.454,0.951)
  silkscreen extent -0.66,-1.51 0.97,1.51
SOT-323-3_L2.0-W1.3-P1.30-LS2.1-BR [mm]
  rect 0.936x0.5 smd paste+0 mask+0.051: 1(457.848,-343.512) 2(457.848,-342.212) 3(456.052,-342.862)
  silkscreen extent 456.25,-343.99 457.65,-341.74
SOT-666-6_L1.6-W1.2-P0.50-LS1.6-BL [mm]
  rect 0.3x0.5 smd paste+0 mask+0.051: 1(470.393,-420.508) 2(470.893,-420.508) 3(471.393,-420.508) 4(471.393,-419.008) 5(470.893,-419.008) 6(470.393,-419.008)
  silkscreen extent 469.68,-420.77 471.77,-419.08
SOT-666-6_L1.6-W1.2-P0.50-LS1.6-BR [mm]
  rect 0.85x0.3 smd paste+0 mask+0.051: 1(0.72,-0.49) 2(0.72,0.01) 3(0.72,0.51) 4(-0.73,0.51) 5(-0.73,0.01) 6(-0.73,-0.49)
  silkscreen extent -0.66,-0.99 1.06,0.91
"SW_SMD_1.27MM X 4 copal" [mm] "SW_SMD_1.27MM X 4 copal"
  rect 0.76x1.27 smd: 1(-1.905,-3.81) 2(-0.635,-3.81) 3(0.635,-3.81) 4(1.905,-3.81) 5(1.905,3.81) 6(0.635,3.81) 7(-0.635,3.81) 8(-1.905,3.81)
  silkscreen extent -3.4,-2.8 3.4,2.8, body extent -3.3,-4 3.3,4, height 2.52
TO-263-2_L10.2-W8.5-P2.54-LS15.2-TL [mm]
  rect 3.5x1.5 smd paste+0 mask+0.051: 1(-6.67,2.54) 3(-6.67,-2.54)
  rect 8x11 smd paste+0 mask+0.051: 2(4.634,0)
  silkscreen extent -2.03,-5.33 0.51,5.33
TP06R#1 [mm] "Testpoint, round, d=0.6mm"
  round 0.6 smd paste-1: 1(0,0)
TP06R#2 [mm] "Testpoint, round, d=0.6mm"
  round 0.6 smd far side paste-1: 1(0,0)
TP_1x0.6 [mm] "Test Point round, diam=1.2mm, drill=0.7mm"
  round 1 hole 0.6: 1(0,0)
  silkscreen extent -0.8,-0.8 0.8,0.8, body extent -0.25,-0.25 0.25,0.25
TQFN-48_L7.0-W7.0-P0.50-BL-EP5.5 [mm]
  rect 0.25x0.6 smd paste-100 mask+0.05: 1(-2.75,-3.257) 2(-2.25,-3.257) 3(-1.75,-3.257) 4(-1.25,-3.257) 5(-0.75,-3.257) 6(-0.25,-3.257) 7(0.25,-3.257) 8(0.75,-3.257) 9(1.25,-3.257) 10(1.75,-3.257) 11(2.25,-3.257) 12(2.75,-3.257) 25(2.75,3.543) 26(2.25,3.543) 27(1.75,3.543) 28(1.25,3.543) 29(0.75,3.543) 30(0.25,3.543) 31(-0.25,3.543) 32(-0.75,3.543) 33(-1.25,3.543) 34(-1.75,3.543) 35(-2.25,3.543) 36(-2.75,3.543)
  rect 0.6x0.25 smd paste-100 mask+0.05: 13(3.4,-2.607) 14(3.4,-2.107) 15(3.4,-1.607) 16(3.4,-1.107) 17(3.4,-0.607) 18(3.4,-0.107) 19(3.4,0.393) 20(3.4,0.893) 21(3.4,1.393) 22(3.4,1.893) 23(3.4,2.393) 24(3.4,2.893) 37(-3.4,2.893) 38(-3.4,2.393) 39(-3.4,1.893) 40(-3.4,1.393) 41(-3.4,0.893) 42(-3.4,0.393) 43(-3.4,-0.107) 44(-3.4,-0.607) 45(-3.4,-1.107) 46(-3.4,-1.607) 47(-3.4,-2.107) 48(-3.4,-2.607)
  rect 5.5x5.5 smd paste-100 mask+0.05: 49(0,0.143)
  silkscreen extent -3.72,-3.97 3.72,3.87
TSSOP-16_L5.0-W4.4-P0.65-LS6.4-BL [mm]
  oval 0.343x1.731 smd paste+0 mask+0.051: 1(454.88,-345.345) 2(455.53,-345.345) 3(456.18,-345.345) 4(456.83,-345.345) 5(457.48,-345.345) 6(458.13,-345.345) 7(458.78,-345.345) 8(459.43,-345.345) 9(459.43,-339.613) 10(458.78,-339.613) 11(458.13,-339.613) 12(457.48,-339.613) 13(456.83,-339.613) 14(456.18,-339.613) 15(455.53,-339.613) 16(454.88,-339.613)
  silkscreen extent 454.11,-345.49 459.73,-340.71
TVS_LESD5D5.0CT1G [mm]
  rect 0.48x0.4 smd: 1(-0.66,0) 2(0.66,0)
  silkscreen extent -1.6,-0.52 0.6,0.52, body extent -0.8,-0.4 0.8,0.4, height 0.7
VSON-CLIP-8_L5.0-W6.0-P1.27-BL [mm]
  rect 0.7x1.27 smd paste-100 mask+0.051: 1(-1.891,-2.932) 2(-0.623,-2.932) 3(0.649,-2.932) 4(1.919,-2.932)
  rect 0.7x1 smd paste-100 mask+0.051: 5(1.917,3.068) 6(0.647,3.068) 7(-0.623,3.068) 8(-1.893,3.068)
  rect 4.9x4.5 smd paste-100 mask+0.051: 8(0.012,0.457)
  silkscreen extent -2.74,-3.5 2.61,3.07
WE-HCC_1210 [mm] "SMT High Current Cube Inductor, 2-Leads, body 12.1x11.4mm"
  rect 2.9x5.4 smd: 1(-4.95,0) 2(4.95,0)
  silkscreen extent -5.95,-5.95 5.95,5.95, body extent -6.05,-5.7 6.05,5.7, height 9.5
WE-MAPI_3020 [mm] "SMT Shielded Power Inductor, body 3.00 x 3.00 mm"
  rect 1.3x3.4 smd: 1(-1.05,0) 2(1.05,0)
  Top Layer 1 _Signal keep-out region: -0.4,1.7 0.4,1.7 0.4,-1.7 -0.4,-1.7
  body extent -1.5,-1.5 1.5,1.5, height 2.01
WE-MAPI_4020 [mm] "SMT Shielded Power Inductor, body 4.10 x 4.10 mm"
  rect 0.98x3.7 smd: 1(-1.185,0) 2(1.185,0)
  Top Layer 1 _Signal keep-out region: -0.695,1.85 0.695,1.85 0.695,-1.85 -0.695,-1.85
  silkscreen extent -2.15,-2.15 2.15,2.7, body extent -2.05,-2.05 2.05,2.05, height 2.1
WFBGA-200_L14.5-W10.0-BL_MT53D512M32D2DS [mm]
  round 0.35 smd paste+0 mask+0.025: A1(-6.711,-4.163) A2(-6.711,-3.363) A3(-6.711,-2.563) A4(-6.711,-1.763) A5(-6.711,-0.963) A8(-6.711,1.437) A9(-6.711,2.237) A10(-6.711,3.037) A11(-6.711,3.837) A12(-6.711,4.637) AA1(6.289,-4.163) AA2(6.289,-3.363) AA3(6.289,-2.563) AA4(6.289,-1.763) AA5(6.289,-0.963) AA8(6.289,1.437) AA9(6.289,2.237) AA10(6.289,3.037) AA11(6.289,3.837) AA12(6.289,4.637) AB1(6.939,-4.163) AB2(6.939,-3.363) AB3(6.939,-2.563) AB4(6.939,-1.763) AB5(6.939,-0.963) AB8(6.939,1.437) AB9(6.939,2.237) AB10(6.939,3.037) AB11(6.939,3.837) AB12(6.939,4.637) B1(-6.061,-4.163) B2(-6.061,-3.363) B3(-6.061,-2.563) B4(-6.061,-1.763) B5(-6.061,-0.963) B8(-6.061,1.437) B9(-6.061,2.237) B10(-6.061,3.037) B11(-6.061,3.837) B12(-6.061,4.637) C1(-5.411,-4.163) C2(-5.411,-3.363) C3(-5.411,-2.563) C4(-5.411,-1.763) C5(-5.411,-0.963) C8(-5.411,1.437) C9(-5.411,2.237) C10(-5.411,3.037) C11(-5.411,3.837) C12(-5.411,4.637) D1(-4.761,-4.163) D2(-4.761,-3.363) D3(-4.761,-2.563) D4(-4.761,-1.763) D5(-4.761,-0.963) D8(-4.761,1.437) D9(-4.761,2.237) D10(-4.761,3.037) D11(-4.761,3.837) D12(-4.761,4.637) E1(-4.111,-4.163) E2(-4.111,-3.363) E3(-4.111,-2.563) E4(-4.111,-1.763) E5(-4.111,-0.963) E8(-4.111,1.437) E9(-4.111,2.237) E10(-4.111,3.037) E11(-4.111,3.837) E12(-4.111,4.637) F1(-3.461,-4.163) F2(-3.461,-3.363) F3(-3.461,-2.563) F4(-3.461,-1.763) F5(-3.461,-0.963) F8(-3.461,1.437) F9(-3.461,2.237) F10(-3.461,3.037) F11(-3.461,3.837) F12(-3.461,4.637) G1(-2.811,-4.163) G2(-2.811,-3.363) G3(-2.811,-2.563) G4(-2.811,-1.763) G5(-2.811,-0.963) G8(-2.811,1.437) G9(-2.811,2.237) G10(-2.811,3.037) G11(-2.811,3.837) G12(-2.811,4.637) H1(-2.161,-4.163) H2(-2.161,-3.363) H3(-2.161,-2.563) H4(-2.161,-1.763) H5(-2.161,-0.963) H8(-2.161,1.437) H9(-2.161,2.237) H10(-2.161,3.037) H11(-2.161,3.837) H12(-2.161,4.637) J1(-1.511,-4.163) J2(-1.511,-3.363) J3(-1.511,-2.563) J4(-1.511,-1.763) J5(-1.511,-0.963) J8(-1.511,1.437) J9(-1.511,2.237) J10(-1.511,3.037) J11(-1.511,3.837) J12(-1.511,4.637) K1(-0.861,-4.163) K2(-0.861,-3.363) K3(-0.861,-2.563) K4(-0.861,-1.763) K5(-0.861,-0.963) K8(-0.861,1.437) K9(-0.861,2.237) K10(-0.861,3.037) K11(-0.861,3.837) K12(-0.861,4.637) N1(1.089,-4.163) N2(1.089,-3.363) N3(1.089,-2.563) N4(1.089,-1.763) N5(1.089,-0.963) N8(1.089,1.437) N9(1.089,2.237) N10(1.089,3.037) N11(1.089,3.837) N12(1.089,4.637) P1(1.739,-4.163) P2(1.739,-3.363) P3(1.739,-2.563) P4(1.739,-1.763) P5(1.739,-0.963) P8(1.739,1.437) P9(1.739,2.237) P10(1.739,3.037) P11(1.739,3.837) P12(1.739,4.637) R1(2.389,-4.163) R2(2.389,-3.363) R3(2.389,-2.563) R4(2.389,-1.763) R5(2.389,-0.963) R8(2.389,1.437) R9(2.389,2.237) R10(2.389,3.037) R11(2.389,3.837) R12(2.389,4.637) T1(3.039,-4.163) T2(3.039,-3.363) T3(3.039,-2.563) T4(3.039,-1.763) T5(3.039,-0.963) T8(3.039,1.437) T9(3.039,2.237) T10(3.039,3.037) T11(3.039,3.837) T12(3.039,4.637) U1(3.689,-4.163) U2(3.689,-3.363) U3(3.689,-2.563) U4(3.689,-1.763) U5(3.689,-0.963) U8(3.689,1.437) U9(3.689,2.237) U10(3.689,3.037) U11(3.689,3.837) U12(3.689,4.637) V1(4.339,-4.163) V2(4.339,-3.363) V3(4.339,-2.563) V4(4.339,-1.763) V5(4.339,-0.963) V8(4.339,1.437) V9(4.339,2.237) V10(4.339,3.037) V11(4.339,3.837) V12(4.339,4.637) W1(4.989,-4.163) W2(4.989,-3.363) W3(4.989,-2.563) W4(4.989,-1.763) W5(4.989,-0.963) W8(4.989,1.437) W9(4.989,2.237) W10(4.989,3.037) W11(4.989,3.837) W12(4.989,4.637) Y1(5.639,-4.163) Y2(5.639,-3.363) Y3(5.639,-2.563) Y4(5.639,-1.763) Y5(5.639,-0.963) Y8(5.639,1.437) Y9(5.639,2.237) Y10(5.639,3.037) Y11(5.639,3.837) Y12(5.639,4.637)
  silkscreen extent -7.44,-5.39 7.44,5.31
WLCSP-20_L2.0-W1.6-R5-C4-P0.40-TL [mm]
  round 0.2 smd paste-100 mask+0.05: A1(-0.47,0.8) A2(-0.07,0.8) A3(0.33,0.8) A4(0.73,0.8) B1(-0.47,0.4) B2(-0.07,0.4) B3(0.33,0.4) B4(0.73,0.4) C1(-0.47,0) C2(-0.07,0) C3(0.33,0) C4(0.73,0) D1(-0.47,-0.4) D2(-0.07,-0.4) D3(0.33,-0.4) D4(0.73,-0.4) E1(-0.47,-0.8) E2(-0.07,-0.8) E3(0.33,-0.8) E4(0.73,-0.8)
  silkscreen extent -0.99,-1 0.94,1
WSON-8_L6.0-W8.0-P1.27-BL-EP [mm]
  rect 0.6x1.2 smd paste+0 mask+0.051: 1(-1.905,-3.75) 2(-0.635,-3.75) 3(0.635,-3.75) 4(1.905,-3.75) 5(1.905,3.85) 6(0.635,3.85) 7(-0.635,3.85) 8(-1.905,3.85)
  rect 4.3x3.4 smd paste+0 mask+0.051: 9(0,0.05)
  silkscreen extent -3,-4.45 3,4.05

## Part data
1 2 3 4 5 6: library part CMP-001-00016-6, "10uF 50V X5R ±10% 1206 Multilayer Ceramic Capacitors MLCC - SMD/SMT ROHS", Capacitor Type=Ceramic, Case/Package=1206, LCSC=C13585, Max Operating Temperature=125°C, Min Operating Temperature=-55°C, Tolerance=10%, Voltage Rating=50
C1 C2 C3 C4 C28 C107 C182 C651 C652 C654 C657 C662 C665 C666: library part CMP-03422-001280-2, "CAP CER 0.1UF 25V X5R 0201"
C5 C15 C16 C17 C23 C30 C32 C34 C35 C203 C204 C226 C228 C241 C242 C243 C244 C250 C258 C259 C261 C269 C270 C279 C280 C281 C286 C287 C288 C292 C293 C294 C297 C301 C307 C312 C454 C455 C456 C457 C458 C459 C461 C464 C468 C473 C519 C559 C562 C564 C565 C566 C568 C569 C570 C571 C572 C573 C574 C612 C615 C616 C617 C629 C632: library part CMP-2010-00672-2, "Cap Ceramic 100nF 10V X5R ±10% Pad SMD 0201 +85°C T/R", Case Code (Metric)=0603, Case/Package=0201, Dielectric=X5R, LCSC=C49062, Min Operating Temperature=-55°C, Package Quantity=1, Tolerance=10%, Voltage Rating=10V
C6 C7 C8 C9 C10 C11 C12 C13 C14 C176 C194 C215 C227 C229 C236 C240 C248 C256 C257 C260 C265 C266 C275 C277 C278 C282 C284 C285 C290 C291 C295 C296 C298 C299 C300 C302 C303 C305 C308 C310 C460 C462 C465 C466 C469 C470 C471 C472 C613 C614: library part CMP-03422-000660-2, "1uF 6.3V X5R ±20% 0201 Multilayer Ceramic Capacitors MLCC - SMD/SMT ROHS", Capacitance="1 uF", LCSC=C53067, Manufacturer=Yageo, Manufacturer Part Number=CC0201MRX5R5BB105, Package=CC0201-BA, Temperature="-55°C to +85°C", Temperature Characteristic=X5R, Temperature Coefficient=15%, Temperature Range High=+85°C, Temperature Range Low=-55°C, Tolerance=0.2, Voltage Rating="6.3 V"
C18 C36 C37 C38 C223 C224 C234 C235 C237 C238 C245 C246 C247 C253 C254 C267 C268 C273 C274 C494 C495 C496 C497 C498 C502 C503 C504 C505 C506 C508 C511 C512 C513 C514 C515 C518: library part CMP-06035-063649-1, "10V 22uF X5R ±20% 0603 Multilayer Ceramic Capacitors MLCC - SMD/SMT ROHS", LCSC=C86295
C19: library part CMP-2008-02504-1, "04023A560KAT2A", Manufacturer="AVX Interconnect / Elco"
C20 C21 C321 C326 C348 C354: library part CMP-03020-034663-1, "CAP CER 10UF 25V X5R 0805", Capacitance=10uF, Case Code (Imperial)=0805, Case Code (Metric)=2012, Dielectric=X5R, Dielectric Material=Ceramic, Max Operating Temperature=85°C, Min Operating Temperature=-55°C, Tolerance=10%, Voltage=25V
C22 C329 C330 C489 C674 C682: library part CMP-1035-02595-8, "Chip Multilayer Ceramic Capacitors for General Purpose, 0603, 0.10uF, X7R, 15%, 10%, 100V", Capacitance=100nF, Case Code (Imperial)=0603, Case Code (Metric)=1608, Dielectric=X7R, Max Operating Temperature=125°C, Min Operating Temperature=-55°C, Package Quantity=1, Tolerance=10%, Voltage=100V
C24 C25 C26 C29 C49 C52 C58 C59 C60 C72 C75 C77 C315 C316 C339 C340 C350 C367 C368 C393 C394 C413 C414 C431 C432 C442 C444 C446 C637 C655 C658 C659 C660 R126: library part CMP-00621-81932632-1, "CC0603KRX5R7BB106 Multilayer Ceramic Capacitor, 10 uF, 16 V, ± 10%, X5R, 0603 [1608 Metric]", Capacitance=10µF, Case/Package=0603, Dielectric=X5R, Max Operating Temperature=85°C, Min Operating Temperature=-55°C, Tolerance=10%, Voltage Rating=16V
C27 C544 C649 C650 C653 C656 C661 C663 C664: library part CMP-03020-034679-1, "CAP CER 1UF 16V X5R 0402", Capacitance=1uF, Case Code (Imperial)=0402, Case Code (Metric)=1005, Dielectric=X5R, Dielectric Material=Ceramic, Max Operating Temperature=85°C, Min Operating Temperature=-55°C, Tolerance=10%, Voltage Rating=16V
C31 C33: library part CMP-03020-024161-1, "C0402 18 pF X8R 5.00% 50 V", Capacitance="18 pF", LCSC=C1549, Manufacturer=Kemet, Manufacturer Part Number=0402CG180J500NT, Package=C0402-BB, Temperature="-55°C to +125°C", Temperature Characteristic=X8R, Temperature Coefficient=15%, Temperature Range High=+125°C, Temperature Range Low=-55°C, Tolerance=0.05, Voltage Rating="50 V"
C39: library part CMP-1037-04923-3, "Chip Multilayer Ceramic Capacitors for General Purpose, 1206, 4.7uF, X7R, 15%, 10%, 50V", Capacitance=4.7uF, Case Code (Imperial)=1206, Case Code (Metric)=3216, Dielectric=X7R, Max Operating Temperature=125°C, Min Operating Temperature=-55°C, Package Quantity=2000, Tolerance=10%, Voltage=50V
C40: library part CMP-1036-04423-3, "CAP CER 0.1UF 50V X7R 0805", Capacitance="0.10 μF", Manufacturer=KEMET, Package=C0805C-DN, Temperature="-55°C to +125°C", Temperature Characteristic=X7R, Temperature Coefficient=30ppm/°C, Temperature Range High=+125°C, Temperature Range Low=-55°C, Tolerance=0.2, Voltage Rating="50 V"
C41 C42 C46 C53 C54 C56 C57 C61 C63 C64 C65 C66 C67 C70 C71 C73 C74 C76 C158 C159 C160 C162 C164 C165 C166 C180 C181 C338 C366 C412 C430: library part CMP-06035-006914-1, "Chip Multilayer Ceramic Capacitors for General Purpose, 0603, 22uF, X5R, 15%, 20%, 6.3V"
C43 C44: library part CMP-1036-04949-2, Manufacturer=Kemet, Part Number=C0805C476M7PACTU
C45 C51 C62 C157 C163 C174 C175 C177 C178 C325 C341 C388 C392 C402 C415 C433 C551 C553 C554 C555 C556 C557 C558: library part CMP-2008-02081-2, "CAP CER 1UF 10V X5R 0402", Capacitance=1uF, Case Code (Imperial)=0402, Case Code (Metric)=1005, Dielectric=X5R, Dielectric Material=Ceramic, Max Operating Temperature=85°C, Min Operating Temperature=-55°C, Package Quantity=1, Tolerance=10%, Voltage=10V
C47 C186 C195 C487 C527 C602: library part CMP-2000-06331-1, "Chip Capacitor, 0.1 uF, +/- 10%, 10 V, -55 to 125 degC, 0402 (1005 Metric), RoHS, Tape and Reel", Capacitance=100000pF, Case Size/Dimension=0402, Dielectric=X7R, Manufacturer=Murata, Package Description="2-Pin Surface Mount Device, Body 1 x 0.5 mm", Rated Voltage=10V, Tolerance (%)=±10%
C48 C526 C537 C601 C626: library part CMP-1036-04630-2, "CAP CER 0.47UF 10V X7R 0805 / C0805C474J8RACTU", Capacitance="0.47 μF", Manufacturer=KEMET, Manufacturer Part Number=C0805C474J8RACTU, Package=C0805C-DN, Temperature="-55°C to +125°C", Temperature Characteristic=X7R, Temperature Coefficient=30ppm/°C, Temperature Range High=+125°C, Temperature Range Low=-55°C, Tolerance=0.05, Voltage Rating="10 V"
C50 C68 C161 C173 C486 C552: library part CMP-03020-034697-1, "CAP CER 22UF 10V X5R 0805", Capacitance=22uF, Case Code (Imperial)=0805, Case Code (Metric)=2012, Dielectric=X5R, Dielectric Material=Ceramic, Max Operating Temperature=85°C, Min Operating Temperature=-55°C, Tolerance=20%, Voltage=10V
C55 C69: library part CMP-2008-03415-2, "Cap Ceramic 100pF 50V C0G 5% Pad SMD 0402 125C Automotive T/R", Capacitance="100 pF", Manufacturer=Kemet, Manufacturer Part Number=C0402C101J5GACAUTO, Package=C0402-BB, Temperature="-55°C to +125°C", Temperature Characteristic=C0G, Temperature Coefficient=15%, Temperature Range High=+125°C, Temperature Range Low=-55°C, Tolerance=0.05, Voltage Rating="50 V"
C78 C79 C80 C81 C82 C83 C84 C85 C86 C87 C89 C90 C91 C92 C93 C94 C95 C96 C98 C99 C100 C101 C102 C103 C104 C105 C108 C111 C112 C113 C114 C115 C116 C117 C118 C119 C120 C122 C123 C124 C125 C126 C127 C128 C129 C130 C131 C134 C135 C136 C137 C138 C139 C140 C141 C142 C143 C144 C145 C146 C147 C148 C149 C150 C151 C152 C153 C154 C155 C156 C183 C190 C191: library part CMP-03422-000660-2, "CAP CER 1UF 6.3V X5R 0201", Capacitance="1 uF", Manufacturer=Yageo, Manufacturer Part Number=CC0201MRX5R5BB105, Package=CC0201-BA, Temperature="-55°C to +85°C", Temperature Characteristic=X5R, Temperature Coefficient=15%, Temperature Range High=+85°C, Temperature Range Low=-55°C, Tolerance=0.2, Voltage Rating="6.3 V"
C88 C97 C106 C121 C132 C133: library part CAP1648, Manufacturer 1="TDK Corporation", Manufacturer 2=Murata, Manufacturer 3="Samsung Electro-Mechanics", Manufacturer Part Number 1=C1608X5R1A226M080AC, Manufacturer Part Number 2=GRM188R61A226ME15D, Manufacturer Part Number 3=CL10A226MP8NUNE, Operating Temperature="-55C to +85C", Package=0603, Supplier Part Number 1=2525091, Temperature Coefficient=X5R, Tolerance=20%, Voltage=10V
C109: library part CAP2712, Manufacturer 1="Murata Electronics", Manufacturer Part Number 1=GRM033R61A104KE15D, Operating Temperature="-55C to +85C", Package=0201, Supplier Part Number 1=490-5881-2-ND, Temperature Coefficient=X5R, Tolerance=10%, Voltage=10V
C110: library part CAP2679, Manufacturer 1=Murata, Manufacturer Part Number 1=GRM033R60J105MEA2D, Operating Temperature="-55C to +85C", Package=0201, Supplier Part Number 1=490-7229-2-ND, Temperature Coefficient=X5R, Tolerance=20%, Voltage=6.3V
C167 C168 C169 C171 C172: library part CMP-03422-000732-3, "CAP CER 2.2UF 16V X5R 0402", Capacitance=2.2uF, Case Code (Imperial)=0402, Case Code (Metric)=1005, Dielectric=X5R, Max Operating Temperature=85°C, Min Operating Temperature=-55°C, Package Quantity=5000, Tolerance=10%, Voltage Rating=16V
C170 C314: library part CMP-2008-01247-1, Manufacturer=Vitramon, Part Number=VJ0402Y102KXXPW1BC
C179: library part CMP-03422-000819-1, "CAP CER 4.7UF 16V X5R 0402", Capacitance="4.7 uF", Manufacturer=YAGEO, Manufacturer Part Number=CC0402MRX5R7BB475, Package=CC0402, Temperature="-55°C to +125°C", Temperature Characteristic=X5R, Temperature Coefficient=30ppm/°C, Temperature Range High=+125°C, Temperature Range Low=-55°C, Tolerance=0.2, Voltage Rating="16 V"
C184 C185 C529 C530: library part CMP-06035-027412-1, "Chip Multilayer Ceramic Capacitors for General Purpose, 1206, 22uF, X6S, 22%, 20%, 25V / GRM31CC81E226ME11K", Capacitance=22uF, Dielectric=X6S, Tolerance=20%, Voltage Rating (DC)=25V
C187 C347 C492 C528 C603: library part CMP-08246-001970-1, "Cap Ceramic 2.2nF 50V X7R 10% Pad SMD 0402 +125°C Automotive T/R", Capacitance=2.2nF, Case Code (Imperial)=0402, Case Code (Metric)=1005, Dielectric=X7R, Max Operating Temperature=125°C, Min Operating Temperature=-55°C, Package Quantity=1, Ratings=AEC-Q200, Tolerance=10%, Voltage Rating=50V
C188 C189: library part CMP-03020-004605-1, "CAP CER 10UF 25V X7R 1206 / C1206C106K3RACAUTO", Capacitance=10uF, Manufacturer=KEMET, Manufacturer Part Number=C1206C106K3RACAUTO, Package=C1206C-EH, Temperature="-55°C to +125°C", Temperature Characteristic=X7R, Temperature Coefficient=15%, Temperature Range High=+125°C, Temperature Range Low=-55°C, Tolerance=10%, Voltage Rating=25V
C192: library part CMP-14477-001428-2, Capacitance=330pF, Case Code (Imperial)=0402, Case Code (Metric)=1005, Dielectric=C0G, Max Operating Temperature=125°C, Min Operating Temperature=-55°C, Package Quantity=1, Tolerance=5%, Voltage Rating=50V
C193: library part CMP-2008-04219-1, Manufacturer=Murata
C196 C197 C198 C199 C200 C201 C434 C435 C520 C521 C590 C592: library part CMP-2006-01140-1, Manufacturer=Vitramon, Part Number=VJ0603Y104MXXAC
C202 C353 C490 C491 C522 C523 C524 C525 C531 C532 C533 C534 C535 C536 C538 C539 C540 C597 C600 C620 C621 C622 C623 C624 C625 C635 C636 C638 C639 C640: library part CMP-1037-04994-1, "CAP 22uF 16V -20% to +80% 1206 (3216 Metric) Thickness 1.9mm SMD", Case-EIA=1206, Case-Metric=3216, Rated Voltage="16 V", Tolerance="-20% to +80%"
C205: library part CMP-2007-01741-1, "VJ-0805Y333KXBMT", Manufacturer=Vitramon
C206: library part CMP-2008-04196-1, "GRM1555C1E330JA01D", Manufacturer=Murata
C207 C208 C210 C211 C213 C214: library part CMP-001-00001-6, "Chip Capacitor, 0.1 uF, +/- 5%, 16 V, 0402 (1005 Metric)", Capacitor Type=Ceramic, Case/Package=0402, Max Operating Temperature=125°C, Min Operating Temperature=-55°C, Tolerance=5%, Voltage Rating=16V
C209 C212: library part CMP-03422-000819-1, "CAP CER 4.7UF 16V X5R 0402", Capacitance="4.7 uF", Manufacturer=YAGEO, Package=CC0402, Temperature="-55°C to +125°C", Temperature Characteristic=X5R, Temperature Coefficient=30ppm/°C, Temperature Range High=+125°C, Temperature Range Low=-55°C, Tolerance=0.2, Voltage Rating="16 V"
C216: library part CMP-001-00056-4, "Chip Capacitor, 2,2µF +/-20%, 10V, 0402, Thickness 0.6 mm", Case/Package=0402, Max Operating Temperature=85°C, Min Operating Temperature=-55°C, Tolerance=10%, Voltage Rating=10V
